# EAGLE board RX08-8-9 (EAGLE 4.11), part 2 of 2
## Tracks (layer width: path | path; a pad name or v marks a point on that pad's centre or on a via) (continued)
N$100 (continued)
  Bottom 0.254: E19.5 142.88,85.72 144.78,83.82 177.8,83.82 179.71,85.72 E16.2
N$101  (via drill 0.61)
  Top 0.254: v123.19,59.69 123.19,80.64 121.28,80.64 120.02,79.38 E25.12
  Bottom 0.254: E36.11 41.27,47.62 42.55,47.62 E36.12 43.81,48.9 45.09,50.16 49.53,50.16 57.78,58.42 99.06,58.42 100.97,60.33 122.56,60.33 v123.19,59.69
N$102
  Bottom 0.254: E31.13 97.16,78.11 98.42,76.83 101.6,76.83 102.87,78.11 108.58,78.11 E25.8
N$103  (via drill 0.61)
  Top 0.254: v163.83,82.55 166.37,85.09 166.37,95.25 171.45,100.33 171.45,102.87 172.09,103.5 176.53,103.5 176.53,91.44 177.8,90.17 177.8,87.63 E16.3
  Bottom 0.254: v163.83,82.55 149.86,82.55 147.96,80.64 141.6,80.64 140.34,79.38 E19.9
N$104
  Bottom 0.254: E10.6 196.22,100.97 197.49,99.69 206.38,99.69 207.65,100.97 E10.1
N$105
  Bottom 0.254: E10.10 198.75,93.34 200.03,93.34 E10.11 201.29,93.34 202.56,93.34 E10.12
N$106  (via drill 0.61)
  Top 0.254: IC7.2 66.67,100.97 67.94,100.97 IC7.1 | v182.88,97.16 181.61,98.42 181.61,106.68 177.16,111.12 v121.92,111.12 | v118.11,109.86 v113.03,104.78
  Bottom 0.254: v182.88,97.16 189.87,97.16 192.41,94.61 E10.8 | v121.92,111.12 120.65,109.86 v118.11,109.86 | v113.03,104.78 112.39,104.14 71.12,104.14 69.22,102.23 IC7.1
N$107  (via drill 0.61)
  Top 0.254: E16.7 168.28,85.72 169.54,85.72 E16.6 170.18,85.09 171.45,83.82 171.45,76.83 v173.35,74.93 | v219.71,73.03 219.71,76.2 220.98,77.47 E6.9
  Bottom 0.254: v219.71,73.03 182.88,73.03 181.61,71.75 181.61,70.48 174.62,70.48 173.99,71.12 173.99,74.93 v173.35,74.93
N$108  (via drill 0.61)
  Top 0.254: v125.09,96.52 125.09,99.69 124.46,100.33 E26.1 | v153.67,96.52 153.67,88.9 152.4,87.63 E19.1
  Bottom 0.254: v125.09,96.52 v153.67,96.52
N$110  (via drill 0.61)
  Top 0.254: v119.38,98.42 119.38,99.06 117.47,100.97 E26.4 | v154.94,97.16 153.67,98.42 153.67,102.87 150.5,106.05 148.59,106.05 148.59,81.28 149.86,80.01 E19.13
  Bottom 0.254: v119.38,98.42 120.02,97.79 127.64,97.79 128.27,97.16 153.03,97.16 153.67,97.79 154.31,97.79 v154.94,97.16
N$111  (via drill 0.61)
  Top 0.254: v130.18,109.86 123.19,102.87 v123.19,96.52
  Bottom 0.254: v130.18,109.86 211.46,109.86 215.9,105.41 237.49,105.41 237.49,79.38 234.95,76.83 233.04,76.83 231.78,78.11 E6.13 | v123.19,96.52 122.56,95.89 116.2,95.89 114.94,94.61 E26.10
PARITY  (via drill 0.61)
  Top 0.254: E15.13 177.8,66.04 177.8,71.12 E15.2 178.44,71.75 179.71,71.75 E15.1 | v229.87,73.66 229.87,48.26 231.14,46.99 E4.15
  Bottom 0.254: v229.87,73.66 227.97,75.56 183.51,75.56 180.97,73.03 E15.1
PARITY\  (via drill 0.61)
  Top 0.254: v175.26,90.17 176.53,88.9 176.53,67.31 175.26,66.04 E15.12
  Bottom 0.254: v175.26,90.17 171.45,90.17 168.28,93.34 E17.10
RD  (via drill 0.61)
  Top 0.254: 90.17,96.52 90.17,102.87 92.08,104.78 92.08,107.31 62.23,107.31 51.44,96.52 50.8,96.52 46.99,92.71 46.99,87 40.01,87 21.59,68.58 21.59,64.77 34.29,52.07 34.29,31.11 36.2,31.11 37.47,32.38 E35.10 | 90.17,96.52 88.9,95.25 E32.10 | v121.92,82.55 124.46,85.09 E25.1 | v92.71,82.55 90.17,85.09 90.17,96.52
  Bottom 0.254: v121.92,82.55 121.28,83.19 93.34,83.19 v92.71,82.55
RUN
  Top 0.254: IC9.6 64.14,67.94 65.41,67.94 IC9.7
  Bottom 0.254: IC9.7 66.67,67.94 67.94,66.67 81.92,66.67 85.72,62.87 E30.9 87,61.59 88.27,60.33 99.69,60.33 100.33,60.96 125.73,60.96 126.36,60.33 127,60.33 132.08,65.41 142.88,65.41 144.15,64.14 E18.11
RX_12_BIT\
  Top 0.254: R16.2 24.77,22.86 23.5,22.86 R7.1 22.23,22.86 20.95,24.13 13.34,24.13 | 13.34,24.13 12.7,23.5 DRIVE.FF | 13.34,24.13 16.51,27.3 16.51,64.77 17.78,66.04 IC8.3
RX_DATA  (via drill 0.61)
  Top 0.254: v103.5,38.73 103.5,5.71 57.15,5.71 44.45,18.41 44.45,34.29 45.09,34.92 45.09,36.2 48.26,39.37 E35.1
  Bottom 0.254: v103.5,38.73 104.14,38.1 119.38,38.1 121.28,40.01 E22.3 122.56,40.01 123.83,40.01 E22.2
RX_DATA\  (via drill 0.61)
  Top 0.254: R8.1 18.41,22.86 19.68,22.86 R17.2 | v44.45,83.19 46.99,80.64 46.99,43.18 45.72,41.91 E35.2
  Bottom 0.254: 19.05,27.94 13.34,27.94 DRIVE.BB | 19.05,27.94 24.77,27.94 31.75,34.92 40.01,34.92 45.09,40.01 E35.2 | v44.45,83.19 50.16,88.9 55.88,88.9 60.33,93.34 IC7.5 | 19.05,27.94 19.05,24.77 17.78,23.5 R8.1
RX_DONE\
  Top 0.254: R4.1 23.5,48.26 24.77,48.26 R13.2 26.04,48.26 32.38,48.26 E36.8
  Bottom 0.254: DRIVE.X 12.06,33.02 10.79,34.29 9.53,34.29 8.26,35.56 8.26,46.99 20.95,46.99 22.23,48.26 R4.1
RX_ERROR\
  Top 0.254: R14.2 18.41,48.26 19.68,48.26 R5.1
  Bottom 0.254: E36.3 42.55,56.52 41.27,57.78 30.48,57.78 20.95,48.26 R5.1 | DRIVE.J 13.34,48.26 17.14,48.26 R14.2
RX_INIT\
  Top 0.254: R9.1 23.5,35.56 24.77,35.56 R20.1 | IC8.5 15.24,58.42 14.61,57.78 14.61,45.72 12.7,43.81 DRIVE.N
  Bottom 0.254: R9.1 22.23,35.56 20.95,34.29 15.88,34.29 13.34,36.83 12.06,36.83 11.43,37.47 11.43,43.18 12.06,43.18 DRIVE.N
RX_OUT\
  Top 0.254: 29.21,22.86 29.84,22.86 R3.1 | 29.21,22.86 28.57,22.86 R12.2 | 29.21,22.86 29.21,27.94 33.02,31.75 E35.8
  Bottom 0.254: DRIVE.RR 13.34,12.7 22.23,21.59 26.04,21.59 27.3,22.86 R12.2
RX_RUN\
  Bottom 0.254: 64.77,63.5 65.41,63.5 R15.2 | 64.77,63.5 64.14,63.5 61.59,60.96 R6.1 60.33,60.96 32.38,60.96 29.21,57.78 17.78,57.78 13.34,53.34 DRIVE.D | 64.77,63.5 60.96,67.31 IC9.5
RX_SHIFT\
  Top 0.254: R2.1 29.84,35.56 28.57,35.56 R10.2 27.94,34.92 26.67,33.66 26.67,17.78 13.34,17.78 DRIVE.LL
  Bottom 0.254: E35.5 38.1,39.37 38.1,36.2 30.48,36.2 R2.1
RX_TR_REQ\  (via drill 0.61)
  Top 0.254: R11.2 18.41,35.56 19.68,35.56 R1.1 | v36.83,38.73 36.83,53.34 38.1,54.61 E36.5
  Bottom 0.254: v36.83,38.73 34.92,36.83 22.23,36.83 20.95,35.56 R1.1 | DRIVE.T 13.34,38.1 15.88,35.56 17.14,35.56 R11.2
SDN4\  (via drill 0.61)
  Top 0.254: v162.56,56.52 163.83,55.24 163.83,35.56 167.64,31.75 E13.10 | v140.34,60.33 137.79,62.87 E18.8
  Bottom 0.254: v162.56,56.52 158.75,60.33 v140.34,60.33
SER4\  (via drill 0.61)
  Top 0.254: v146.05,54.61 143.51,57.15 143.51,68.58 142.24,69.85 E18.5
  Bottom 0.254: v146.05,54.61 152.4,54.61 152.4,46.35 163.19,35.56 165.1,35.56 169.54,31.11 E13.11
SHIFT  (via drill 0.61)
  Top 0.254: v41.91,83.19 41.91,43.18 40.64,41.91 E35.4
  Bottom 0.254: v41.91,83.19 41.91,96.52 88.9,96.52 93.34,100.97 E32.3
STR2\  (via drill 0.61)
  Top 0.254: v152.4,21.59 149.86,21.59 149.86,60.96 148.59,62.23 148.59,68.58 149.86,69.85 E18.2
  Bottom 0.254: v152.4,21.59 168.91,21.59 172.09,18.41 E12.12
TR_SKIP  (via drill 0.61)
  Top 0.254: v119.38,104.78 119.38,102.87 E26.3 | 151.13,104.14 152.4,102.87 E20.1 | 151.13,104.14 v150.5,104.78 | 151.13,104.14 151.13,73.66 152.4,72.39 E18.1
  Bottom 0.254: v119.38,104.78 120.02,104.14 149.86,104.14 v150.5,104.78
VCC
  Top 0.508: C37.1 55.88,81.92 50.8,87 50.8,92.08 C38.1 | R18.2 76.2,81.92 73.66,84.45 73.66,94.61 C34.1 | C39.1 27.94,61.59 32.38,66.04 32.38,71.12 C40.+ | C36.1 50.16,48.26 48.9,48.26 E36.14 48.26,46.99 49.53,45.72 49.53,36.2 50.8,34.92 C35.1 | 21.59,38.1 22.23,38.1 R4.2 | 21.59,38.1 20.95,38.1 R5.2 20.32,37.47 21.59,36.2 21.59,25.4 | 21.59,25.4 22.23,25.4 R9.2 23.5,25.4 24.77,25.4 R20.2 | 21.59,25.4 20.95,25.4 R1.2 | R3.2 30.48,13.34 31.75,14.61 31.75,23.5 30.48,24.77 R2.2 | 21.59,38.1 21.59,57.15 22.86,58.42 IC8.8 | E8.14 208.28,64.77 207.01,66.04 207.01,76.2 205.74,77.47 IC10.8 | E10.14 208.28,92.71 212.09,88.9 212.09,81.92 210.82,80.64 C9.1 | E2.10 220.98,19.05 220.98,16.51 E1.5 | C1.1 233.68,9.53 232.41,10.79 232.41,17.78 231.14,19.05 E2.14 | 232.41,36.2 233.68,34.92 C3.1 | 232.41,36.2 232.41,43.18 233.68,44.45 E4.16 | E6.12 228.6,80.01 226.06,82.55 226.06,85.09 E6.4 | 234.95,60.33 233.68,61.59 233.68,62.23 E5.14 | 234.95,60.33 236.22,59.05 R19.1 | 234.95,81.92 234.95,85.72 235.59,86.36 235.59,93.98 236.22,94.61 C7.1 | 234.95,81.92 236.22,80.64 C6.1 | 234.95,81.92 234.95,66.67 236.22,65.41 C5.1 | 234.95,60.33 234.95,48.9 236.22,47.62 C4.1 | 232.41,36.2 232.41,23.5 233.68,22.23 C2.1 | IC3.8 86.36,19.05 85.09,20.32 85.09,30.48 86.36,31.75 IC2.8 | 128.27,30.48 128.27,20.95 129.54,19.68 C21.1 | 128.27,30.48 127,31.75 E22.16 | 128.27,45.72 127,46.99 E23.16 | 128.27,45.72 128.27,30.48 | 128.27,45.72 128.27,62.87 127,64.14 C24.1 127,65.41 128.27,66.67 128.27,73.03 127,74.3 127,79.38 C25.1 127,80.64 128.27,81.92 128.27,93.34 127,94.61 C26.1 | C11.1 185.42,6.99 186.69,8.26 186.69,17.14 185.42,18.41 C12.1
  Top 0.508: E13.16 182.88,29.21 184.15,27.94 184.15,21.59 182.88,20.32 182.88,19.05 E12.16 | 179.07,62.87 179.71,62.87 179.71,64.14 E15.14 | 179.07,62.87 174.62,62.87 170.81,59.05 E14.6 | 179.07,62.87 179.07,55.88 182.88,52.07 E14.16 | C13.1 185.42,32.38 186.69,33.66 186.69,50.16 185.42,51.44 C14.1 | IC5.8 99.06,49.53 97.79,50.8 97.79,57.15 99.06,58.42 99.06,60.96 E30.14 | R6.2 71.12,61.59 73.66,64.14 73.66,69.22 C33.1 | 88.27,56.52 88.27,61.59 E30.10 88.9,63.5 88.9,66.04 91.44,68.58 E30.4 | 88.27,56.52 88.27,51.44 86.36,49.53 IC6.8 | 88.27,56.52 93.34,61.59 E30.12 | C17.1 185.42,99.69 184.15,98.42 184.15,81.92 185.42,80.64 C16.1 185.42,79.38 185.42,78.74 181.61,74.93 181.61,67.94 182.88,66.67 C15.1 | C18.1 154.94,65.41 153.67,66.67 153.67,76.2 152.4,77.47 E19.14 152.4,80.01 154.94,82.55 154.94,84.45 C19.1 154.94,85.72 154.94,94.61 C20.1 | E17.5 172.72,100.33 171.45,99.06 171.45,88.9 172.72,87.63 E16.5 | C30.1 101.6,64.14 102.87,65.41 102.87,74.3 101.6,75.56 101.6,79.38 C31.1 | IC7.8 68.58,92.71 67.31,91.44 67.31,71.12 68.58,69.85 IC9.8
  Bottom 0.508: C32.1 100.97,95.25 100.33,95.25 99.69,94.61 E32.14 98.42,94.61 97.16,95.89 73.66,95.89 | IC7.8 69.22,94.61 69.85,95.25 73.03,95.25 C34.1 | C34.1 73.66,95.89 | 73.66,95.89 54.61,95.89 51.44,92.71 C38.1 | C34.1 73.66,95.89 | IC8.8 23.5,60.33 24.13,60.96 27.3,60.96 C39.1 | SL1.1 19.05,73.66 19.68,73.03 31.75,73.03 C40.+ 34.29,73.03 46.99,73.03 55.24,81.28 C37.1 | C35.1 50.16,34.29 49.53,34.29 48.9,33.66 E35.14 47.62,32.38 40.64,25.4 31.11,25.4 R2.2 29.84,25.4 28.57,26.67 27.3,26.67 26.04,25.4 R20.2 | 20.95,13.97 19.68,13.97 18.41,12.7 R8.2 | 20.95,13.97 22.23,12.7 R7.2 | 20.95,13.97 28.57,13.97 29.84,12.7 R3.2 | E10.14 208.91,94.61 209.55,95.25 210.19,95.25 C10.1 | E8.14 208.91,64.14 209.55,64.77 210.19,64.77 C8.1 | E1.5 221.62,14.61 222.88,14.61 E1.4 | E1.14 231.78,8.26 232.41,8.89 233.04,8.89 C1.1 | E2.14 231.78,20.95 232.41,21.59 233.04,21.59 C2.1 233.68,22.23 222.88,22.23 221.62,20.95 E2.10 | C4.1 235.59,46.99 234.95,46.35 234.31,46.35 E4.16 | E5.14 234.31,64.14 234.95,64.77 235.59,64.77 C5.1 | E6.14 234.31,79.38 234.95,80.01 235.59,80.01 C6.1 236.22,80.64 230.5,80.64 | 230.5,80.64 229.24,79.38 E6.12 | 230.5,80.64 212.09,80.64 211.46,80.01 C9.1 210.19,80.01 207.01,80.01 206.38,79.38 IC10.8 205.1,79.38 203.2,81.28 187.32,81.28 186.06,80.01 C16.1 | IC3.8 87,18.41 88.27,19.68 97.16,19.68 98.42,18.41 IC4.8 99.69,18.41 100.33,18.41 100.97,19.05 C27.1 | 99.06,34.92 101.6,34.92 C28.1 102.23,34.29 102.87,34.92 117.47,34.92 118.11,34.29 118.11,31.11 125.09,31.11 126.36,32.38 E22.16 127.64,33.66 128.27,34.29 128.91,34.29 C22.1 | 99.06,34.92 88.27,34.92 87,33.66 IC2.8
  Bottom 0.508: 99.06,34.92 99.06,34.29 IC1.8 | E24.14 125.09,64.14 125.73,64.77 126.36,64.77 C24.1 | E23.16 127.64,48.9 128.27,49.53 128.91,49.53 C23.1 | E21.16 127.64,18.41 128.27,19.05 128.91,19.05 C21.1 | E13.16 183.51,31.11 184.15,31.75 184.78,31.75 C13.1 | E11.16 183.51,5.71 184.15,6.35 184.78,6.35 C11.1 | E12.16 183.51,18.41 184.15,19.05 184.78,19.05 C12.1 | E14.16 183.51,51.44 184.15,52.07 184.78,52.07 C14.1 | C15.1 182.25,66.04 181.61,65.41 180.97,65.41 E15.14 | IC5.8 99.69,48.9 100.33,49.53 100.97,49.53 C29.1 | C30.1 100.97,63.5 100.33,63.5 99.69,62.87 E30.14 98.42,62.87 97.16,64.14 87,64.14 | IC9.8 69.22,69.22 69.85,69.85 73.03,69.85 C33.1 74.3,69.85 76.83,67.31 83.82,67.31 87,64.14 | 87,64.14 88.27,62.87 E30.10 | E17.7 168.28,100.97 169.54,99.69 170.81,99.69 172.09,100.97 E17.5 173.35,100.97 174.62,100.97 E17.4 175.9,100.97 177.16,100.97 E17.3 178.44,100.97 179.71,100.97 E17.2 180.97,100.97 182.25,100.97 E17.1 183.51,100.97 184.15,100.97 184.78,100.33 C17.1 185.42,99.69 | E31.14 99.69,79.38 100.33,80.01 100.97,80.01 C31.1 102.23,80.01 102.87,80.64 118.75,80.64 | 118.75,80.64 117.47,79.38 E25.11 | 118.75,80.64 120.02,80.64 121.28,79.38 E25.13 122.56,78.11 123.83,78.11 E25.14 125.09,79.38 125.73,79.38 126.36,80.01 C25.1 | E18.14 153.03,64.14 153.67,64.77 154.31,64.77 C18.1 | E19.12 147.96,79.38 149.22,80.64 150.5,80.64 151.76,79.38 E19.14 | E26.14 125.09,94.61 125.73,95.25 126.36,95.25 C26.1 127,95.89 137.79,95.89 139.06,94.61 E20.9 140.34,93.34 141.6,93.34 E20.10 142.88,94.61 144.15,95.89 150.5,95.89 151.76,94.61 E20.14 153.03,94.61 153.67,95.25 154.31,95.25 C20.1
  Bottom 0.508: 154.94,84.45 151.76,84.45 150.5,85.72 E19.2 | 154.94,84.45 C19.1 154.94,84.45 | 154.94,84.45 170.81,84.45 172.09,85.72 E16.5
WRT  (via drill 0.61)
  Top 0.254: v186.69,60.33 187.96,61.59 187.96,100.97 193.04,106.05 | 193.04,106.05 198.12,106.05 198.12,102.87 E10.5 | 193.04,106.05 193.04,112.39 121.92,112.39 120.65,111.12 120.65,88.9 121.92,87.63 E25.2
  Bottom 0.254: E25.2 121.28,87 120.02,88.27 118.75,88.27 118.11,88.9 68.58,88.9 64.14,93.34 IC7.6 | v186.69,60.33 173.35,60.33 170.18,63.5 E15.10
XDR2
  Top 0.254: E10.2 205.74,100.33 209.55,96.52 209.55,92.71 217.17,85.09 217.17,66.04 218.44,64.77 E5.8
  Bottom 0.254: E5.8 219.07,62.87 220.34,61.59 226.69,61.59 227.97,62.87 E5.12
XDR2\  (via drill 0.61)
  Top 0.254: v188.59,59.69 188.59,53.34 | 188.59,53.34 188.59,24.77 184.15,20.32 184.15,10.79 177.16,10.79 176.53,11.43 176.53,13.97 175.9,14.61 175.9,15.88 175.26,16.51 E12.13 | v44.45,63.5 44.45,35.56 43.18,34.29 E35.12 | E25.9 111.76,77.47 113.03,76.2 113.03,69.85 113.67,69.22 116.2,69.22 116.2,70.48 E24.4 | 188.59,53.34 184.15,53.34 184.15,47.62 180.97,44.45 166.37,44.45 166.37,54.61 162.56,58.42 v162.56,69.22
  Bottom 0.254: v188.59,59.69 189.87,60.96 213.36,60.96 217.81,65.41 219.07,65.41 220.34,64.14 E5.9 221.62,62.87 222.88,62.87 E5.10 | v44.45,63.5 50.8,69.85 59.69,69.85 60.96,71.12 80.01,71.12 83.19,67.94 97.16,67.94 97.79,68.58 97.79,72.39 107.95,72.39 108.58,73.03 114.94,73.03 | 114.94,73.03 116.2,71.75 E24.4 | v162.56,69.22 161.93,68.58 147.96,68.58 147.32,69.22 128.27,69.22 127.64,68.58 121.92,68.58 120.65,69.85 120.65,73.03 114.94,73.03
XFER_REQ  (via drill 0.61)
  Top 0.254: v40.64,63.5 40.64,57.15 E36.4 | v128.27,74.93 131.44,78.11 v131.44,90.17 | E20.12 147.32,92.71 v147.32,90.81 147.32,87.63 E19.3
  Bottom 0.254: v40.64,63.5 55.24,78.11 64.14,78.11 64.77,77.47 64.77,73.66 96.52,73.66 97.16,74.3 127.64,74.3 v128.27,74.93 | v131.44,90.17 132.08,89.53 146.05,89.53 v147.32,90.81

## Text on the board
Bottom: RX08 Floppy Interface | VRS
tPlace: RX08 Floppy Interface | VRS
tNames: GND | VCC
